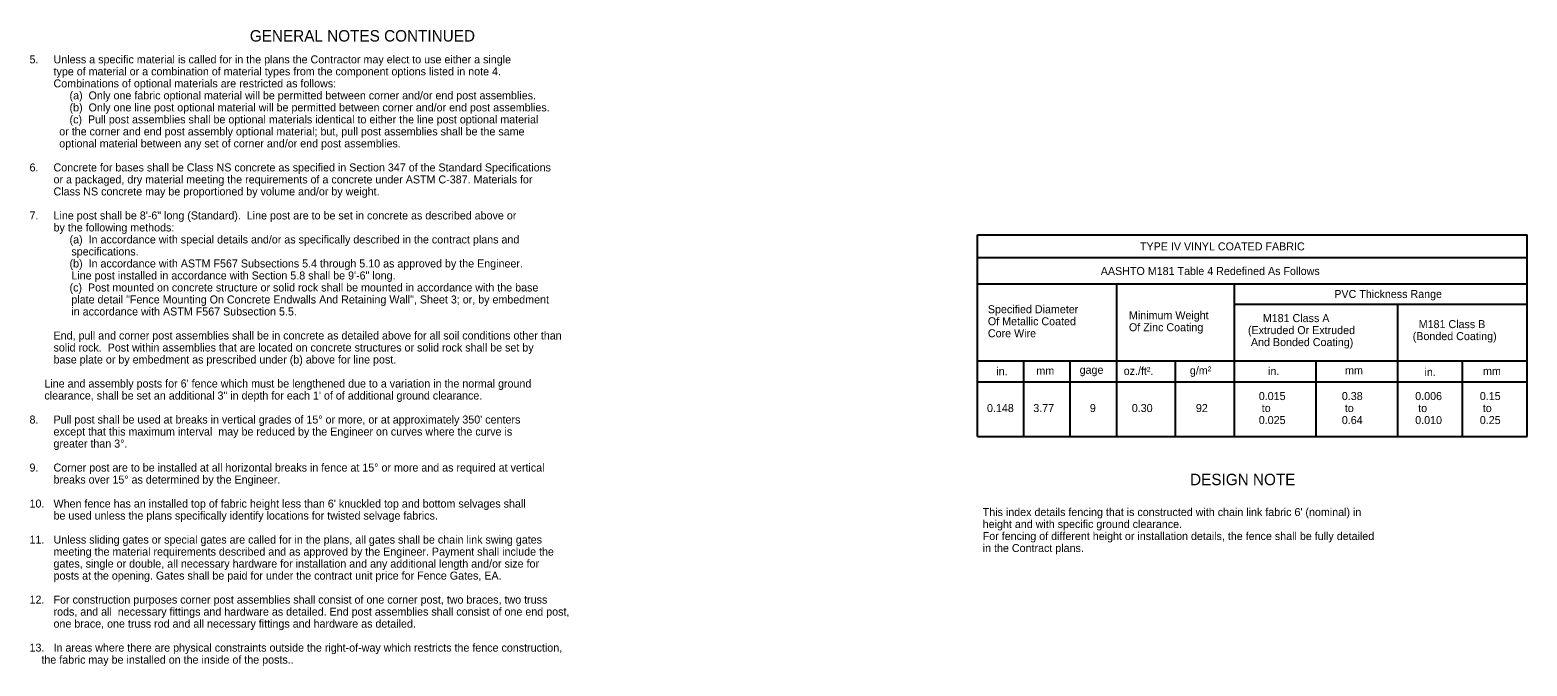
# Model space of a CAD drawing. Extents: x 10080 to 10735, y 10156 to 10434.
import ezdxf

# ---------------------------------------------------------------- set-up
doc = ezdxf.new("R2010")
doc.units = 0
for name, color, linetype in [('Dimension', 7, 'Continuous'), ('SupstrConc', 7, 'Continuous'), ('TextMisc', 7, 'Continuous')]:
    doc.layers.add(name, color=color, linetype=linetype)

msp = doc.modelspace()

# ---------------------------------------------------------------- linework, layer by layer
at = {"layer": 'Dimension'}
for p, q in [((10494.32, 10255.98), (10494.32, 10344.12)), ((10494.32, 10344.12), (10734.67, 10344.12)), ((10734.67, 10255.98), (10734.67, 10344.12)), ((10494.32, 10255.98), (10734.67, 10255.98))]:
    msp.add_line(p, q, dxfattribs=at)
at = {"layer": 'SupstrConc'}
for p, q in [((10494.32, 10334.22), (10734.67, 10334.22)), ((10494.32, 10322.7), (10734.67, 10322.7)), ((10555.24, 10255.98), (10555.24, 10322.7)), ((10606.71, 10255.98), (10606.71, 10322.7)), ((10606.71, 10313.86), (10734.67, 10313.86)), ((10678.17, 10255.98), (10678.17, 10313.86)), ((10494.32, 10289.08), (10734.67, 10289.08)), ((10514.63, 10255.98), (10514.63, 10289.08)), ((10534.93, 10255.98), (10534.93, 10289.08)), ((10580.97, 10255.98), (10580.97, 10289.08)), ((10642.44, 10255.98), (10642.44, 10289.08)), ((10706.42, 10255.98), (10706.42, 10289.08)), ((10494.32, 10279.83), (10734.67, 10279.83))]:
    msp.add_line(p, q, dxfattribs=at)

# ---------------------------------------------------------------- texts
at = {"layer": 'TextMisc'}
for s, height, p in [('GENERAL NOTES CONTINUED', 5, (10176.19, 10428.66)), ('5.', 3.5, (10079.85, 10419.11)), ('Unless a specific material is called for in the plans the Contractor may elect to use either a single', 3.5, (10090.35, 10419.11)), ('type of material or a combination of material types from the component options listed in note 4. ', 3.5, (10090.35, 10413.86)), ('Combinations of optional materials are restricted as follows:', 3.5, (10090.35, 10408.61)), ('(a)  Only one fabric optional material will be permitted between corner and/or end post assemblies.', 3.5, (10097.35, 10403.36)), ('(b)  Only one line post optional material will be permitted between corner and/or end post assemblies.', 3.5, (10097.35, 10398.11)), ('(c)  Pull post assemblies shall be optional materials identical to either the line post optional material', 3.5, (10097.35, 10392.86)), ('          or the corner and end post assembly optional material; but, pull post assemblies shall be the same', 3.5, (10079.85, 10387.61)), ('          optional material between any set of corner and/or end post assemblies.', 3.5, (10079.85, 10382.36)), ('6.', 3.5, (10079.85, 10371.86)), ('or a packaged, dry material meeting the requirements of a concrete under ASTM C-387. Materials for', 3.5, (10090.35, 10366.61)), ('Concrete for bases shall be Class NS concrete as specified in Section 347 of the Standard Specifications', 3.5, (10090.35, 10371.86)), ('Class NS concrete may be proportioned by volume and/or by weight.', 3.5, (10090.35, 10361.36)), ('7.', 3.5, (10079.85, 10350.86)), ('Line post shall be 8\'-6" long (Standard).  Line post are to be set in concrete as described above or ', 3.5, (10090.35, 10350.86)), ('by the following methods:', 3.5, (10090.35, 10345.61)), ('(a)  In accordance with special details and/or as specifically described in the contract plans and', 3.5, (10097.35, 10340.36)), ('      specifications.', 3.5, (10090.35, 10335.11)), ('TYPE IV VINYL COATED FABRIC', 3.5, (10565.41, 10337.33)), ('(b)  In accordance with ASTM F567 Subsections 5.4 through 5.10 as approved by the Engineer.', 3.5, (10097.35, 10329.86)), ('AASHTO M181 Table 4 Redefined As Follows', 3.5, (10548.28, 10326.56)), ('      Line post installed in accordance with Section 5.8 shall be 9\'-6" long.', 3.5, (10090.35, 10324.61)), ('(c)  Post mounted on concrete structure or solid rock shall be mounted in accordance with the base', 3.5, (10097.35, 10319.36)), ('      plate detail "Fence Mounting On Concrete Endwalls And Retaining Wall", Sheet 3; or, by embedment', 3.5, (10090.35, 10314.11)), ('PVC Thickness Range', 3.5, (10650.39, 10316.52)), ('      in accordance with ASTM F567 Subsection 5.5.', 3.5, (10090.35, 10308.86)), ('Specified Diameter', 3.5, (10498.91, 10309.84)), ('Minimum Weight', 3.5, (10560.59, 10307.22)), ('Of Metallic Coated', 3.5, (10498.91, 10304.59)), ('Of Zinc Coating', 3.5, (10560.59, 10301.97)), ('(Extruded Or Extruded', 3.5, (10612.62, 10300.72)), ('     M181 Class A', 3.5, (10612.62, 10305.97)), ('  M181 Class B', 3.5, (10684.69, 10303.34)), ('End, pull and corner post assemblies shall be in concrete as detailed above for all soil conditions other than', 3.5, (10090.35, 10298.36)), ('Core Wire', 3.5, (10498.91, 10299.34)), (' And Bonded Coating)', 3.5, (10612.62, 10295.47)), ('(Bonded Coating)', 3.5, (10684.69, 10298.09)), ('solid rock.  Post within assemblies that are located on concrete structures or solid rock shall be set by', 3.5, (10090.35, 10293.11)), ('base plate or by embedment as prescribed under (b) above for line post.', 3.5, (10090.35, 10287.86)), ('in.', 3.5, (10502.61, 10282.76)), ('mm', 3.5, (10520.11, 10282.95)), ('gage', 3.5, (10539.02, 10283.34)), ('oz./ft².', 3.5, (10558.3, 10282.87)), ('g/m²', 3.5, (10587.23, 10283.08)), ('in.', 3.5, (10621.44, 10282.81)), ('mm', 3.5, (10655.09, 10283.08)), ('in.', 3.5, (10689.83, 10282.4)), ('mm', 3.5, (10715.42, 10282.81)), ("     Line and assembly posts for 6' fence which must be lengthened due to a variation in the normal ground", 3.5, (10079.85, 10277.36)), ('     clearance, shall be set an additional 3" in depth for each 1\' of of additional ground clearance.', 3.5, (10079.85, 10272.11)), ('0.015', 3.5, (10617.36, 10271.88)), ('0.38', 3.5, (10653.69, 10271.88)), ('0.006', 3.5, (10685.77, 10271.88)), ('0.15', 3.5, (10714.02, 10271.88)), ('8.', 3.5, (10079.85, 10261.61)), ("Pull post shall be used at breaks in vertical grades of 15° or more, or at approximately 350' centers", 3.5, (10090.35, 10261.61)), ('0.148', 3.5, (10498.53, 10266.63)), ('3.77', 3.5, (10518.77, 10266.63)), ('9', 3.5, (10543.5, 10266.63)), ('0.30', 3.5, (10561.84, 10266.63)), ('92', 3.5, (10589.86, 10266.63)), ('0.025', 3.5, (10617.36, 10261.38)), (' to', 3.5, (10617.36, 10266.63)), ('0.64', 3.5, (10653.69, 10261.38)), (' to', 3.5, (10653.69, 10266.63)), ('0.010', 3.5, (10685.77, 10261.38)), (' to', 3.5, (10685.77, 10266.63)), ('0.25', 3.5, (10714.02, 10261.38)), (' to', 3.5, (10714.02, 10266.63)), ('except that this maximum interval  may be reduced by the Engineer on curves where the curve is', 3.5, (10090.35, 10256.36)), ('greater than 3°.', 3.5, (10090.35, 10251.11)), ('9.', 3.5, (10079.85, 10240.61)), ('Corner post are to be installed at all horizontal breaks in fence at 15° or more and as required at vertical', 3.5, (10090.35, 10240.61)), ('breaks over 15° as determined by the Engineer.', 3.5, (10090.35, 10235.36)), ('DESIGN NOTE', 5, (10587.33, 10234.65)), ('10.', 3.5, (10079.85, 10224.86)), ("When fence has an installed top of fabric height less than 6' knuckled top and bottom selvages shall", 3.5, (10090.35, 10224.86)), ('be used unless the plans specifically identify locations for twisted selvage fabrics.', 3.5, (10090.35, 10219.61)), ("This index details fencing that is constructed with chain link fabric 6' (nominal) in ", 3.5, (10496.65, 10221.17)), ('height and with specific ground clearance.  ', 3.5, (10496.65, 10215.92)), ('11.', 3.5, (10079.85, 10209.11)), ('Unless sliding gates or special gates are called for in the plans, all gates shall be chain link swing gates', 3.5, (10090.35, 10209.11)), ('For fencing of different height or installation details, the fence shall be fully detailed ', 3.5, (10496.65, 10210.67)), ('meeting the material requirements described and as approved by the Engineer. Payment shall include the', 3.5, (10090.35, 10203.86)), ('in the Contract plans.', 3.5, (10496.65, 10205.42)), ('gates, single or double, all necessary hardware for installation and any additional length and/or size for', 3.5, (10090.35, 10198.61)), ('posts at the opening. Gates shall be paid for under the contract unit price for Fence Gates, EA.', 3.5, (10090.35, 10193.36)), ('12.', 3.5, (10079.85, 10182.86)), ('For construction purposes corner post assemblies shall consist of one corner post, two braces, two truss', 3.5, (10090.35, 10182.86)), ('rods, and all  necessary fittings and hardware as detailed. End post assemblies shall consist of one end post,', 3.5, (10090.35, 10177.61)), ('one brace, one truss rod and all necessary fittings and hardware as detailed.', 3.5, (10090.35, 10172.36)), ('13.', 3.5, (10079.85, 10161.86)), ('    the fabric may be installed on the inside of the posts..', 3.5, (10079.85, 10156.61)), ('In areas where there are physical constraints outside the right-of-way which restricts the fence construction,', 3.5, (10090.35, 10161.86))]:
    msp.add_text(s, height=height, dxfattribs=at).set_placement(p)

doc.saveas('drawing.dxf')
